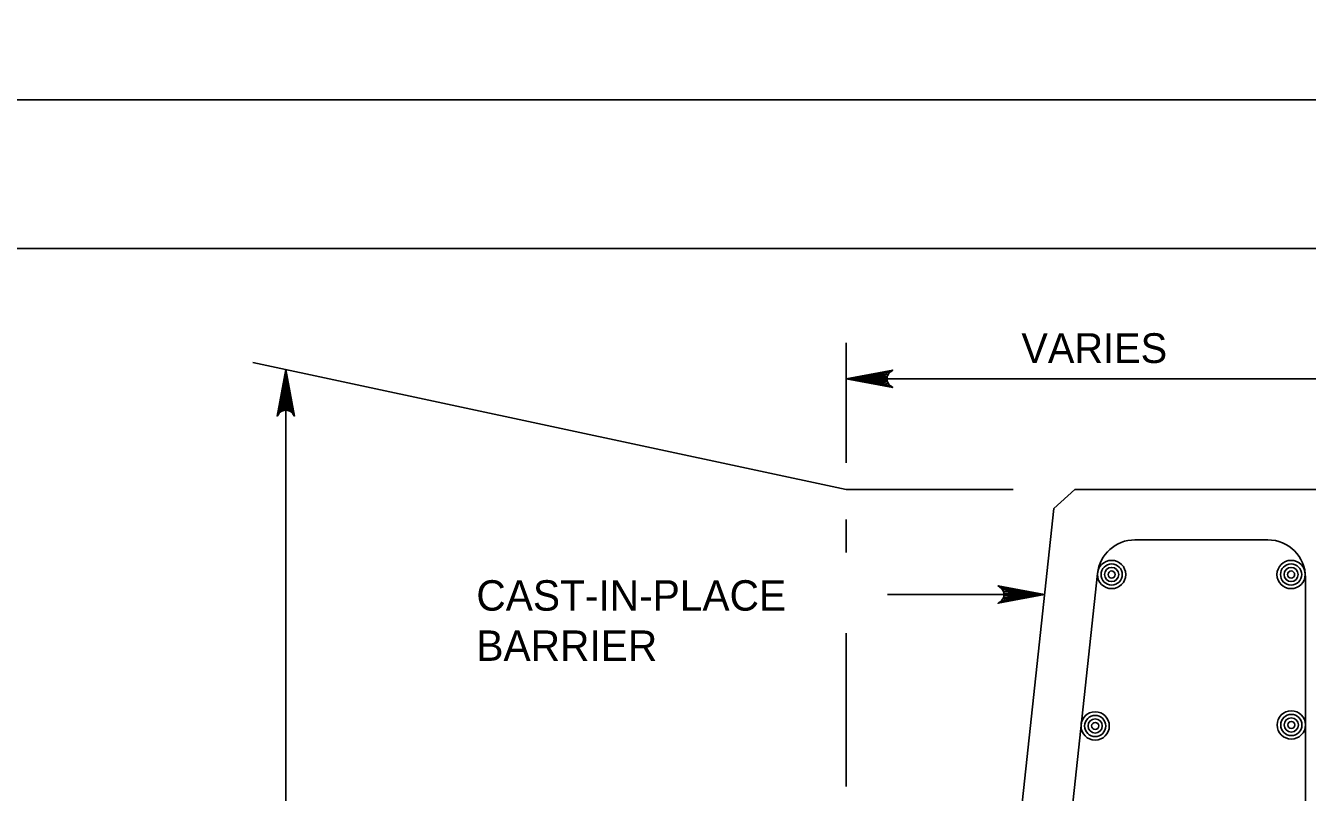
# Model space of a CAD drawing. Extents: x 638167 to 640248, y 296544 to 298920.
# Drawn here: x 639614.9 to 639744.3, y 297662.6 to 297740 of the extents above; entities that cross this region are included whole.
import ezdxf

# ---------------------------------------------------------------- set-up
doc = ezdxf.new("R2010")
doc.units = 0
for name, color, linetype in [('1', 7, 'Continuous'), ('50', 7, 'Continuous'), ('PLT-BNDY', 7, 'Continuous')]:
    doc.layers.add(name, color=color, linetype=linetype)

# ---------------------------------------------------------------- blocks, each defined once
blk = doc.blocks.new('BAR')
at = {"layer": '50'}
for radius in [2, 1.5, 1, 0.5]:
    blk.add_circle((0, 0), radius, dxfattribs=at)

msp = doc.modelspace()

# ---------------------------------------------------------------- linework, layer by layer
at = {"layer": '1'}
for p, q in [((639832.78, 297717.48), (639046.78, 297717.48)), ((639697.78, 297695.85), (639697.78, 297707.94)), ((639697.78, 297693.14), (639637.88, 297705.96)), ((639641.2, 297587.07), (639641.2, 297705.25)), ((639697.78, 297704.31), (639749.22, 297704.31)), ((639697.78, 297693.14), (639714.63, 297693.14)), ((639720.84, 297693.14), (639718.74, 297691.24)), ((639747.31, 297693.14), (639720.84, 297693.14)), ((639718.74, 297691.24), (639710.86, 297618.23)), ((639697.78, 297686.79), (639697.78, 297690.11)), ((639740.33, 297688.06), (639726.93, 297688.06)), ((639723.14, 297684.65), (639714.09, 297600.83)), ((639744.14, 297622.52), (639744.14, 297684.25)), ((639717.8, 297682.53), (639701.93, 297682.53)), ((639697.78, 297663.17), (639697.78, 297678.63))]:
    msp.add_line(p, q, dxfattribs=at)
for points in [[(639641.2, 297705.25), (639642.08, 297700.55), (639641.96, 297700.73), (639641.83, 297700.91), (639641.67, 297701.01), (639641.52, 297701.1), (639641.36, 297701.13), (639641.2, 297701.15), (639641.04, 297701.13), (639640.89, 297701.1), (639640.73, 297701.01), (639640.57, 297700.91), (639640.45, 297700.73), (639640.32, 297700.55), (639641.2, 297705.25), (639640.45, 297700.73), (639640.57, 297700.91), (639641.2, 297705.25), (639640.73, 297701.01), (639640.89, 297701.1), (639641.2, 297705.25), (639641.04, 297701.13), (639641.2, 297701.15), (639641.2, 297705.25), (639641.36, 297701.13), (639641.52, 297701.1), (639641.2, 297705.25), (639641.67, 297701.01), (639641.83, 297700.91), (639641.2, 297705.25), (639641.96, 297700.73)], [(639697.78, 297704.31), (639702.48, 297705.2), (639702.3, 297705.07), (639702.12, 297704.94), (639702.03, 297704.79), (639701.93, 297704.63), (639701.91, 297704.47), (639701.88, 297704.31), (639701.91, 297704.16), (639701.93, 297704), (639702.03, 297703.84), (639702.12, 297703.68), (639702.3, 297703.56), (639702.48, 297703.43), (639697.78, 297704.31), (639702.3, 297703.56), (639702.12, 297703.68), (639697.78, 297704.31), (639702.03, 297703.84), (639701.93, 297704), (639697.78, 297704.31), (639701.91, 297704.16), (639701.88, 297704.31), (639697.78, 297704.31), (639701.91, 297704.47), (639701.93, 297704.63), (639697.78, 297704.31), (639702.03, 297704.79), (639702.12, 297704.94), (639697.78, 297704.31), (639702.3, 297705.07)], [(639717.8, 297682.53), (639713.1, 297681.65), (639713.28, 297681.77), (639713.46, 297681.9), (639713.56, 297682.06), (639713.65, 297682.21), (639713.68, 297682.37), (639713.7, 297682.53), (639713.68, 297682.69), (639713.65, 297682.84), (639713.56, 297683), (639713.46, 297683.16), (639713.28, 297683.28), (639713.1, 297683.41), (639717.8, 297682.53), (639713.28, 297683.28), (639713.46, 297683.16), (639717.8, 297682.53), (639713.56, 297683), (639713.65, 297682.84), (639717.8, 297682.53), (639713.68, 297682.69), (639713.7, 297682.53), (639717.8, 297682.53), (639713.68, 297682.37), (639713.65, 297682.21), (639717.8, 297682.53), (639713.56, 297682.06), (639713.46, 297681.9), (639717.8, 297682.53), (639713.28, 297681.77)]]:
    msp.add_lwpolyline(points, dxfattribs=at)
for centre, start, end in [((639726.93, 297684.25), 90, 173.8367), ((639740.33, 297684.25), 0, 90)]:
    msp.add_arc(centre, 3.81, start, end, dxfattribs=at)
at = {"layer": 'PLT-BNDY'}
for points in [[(639007.78, 298326.48), (639848.78, 298326.48), (639848.78, 297732.48), (639007.78, 297732.48)], [(639007.78, 297732.48), (639848.78, 297732.48), (639848.78, 297138.48), (639007.78, 297138.48)]]:
    msp.add_lwpolyline(points, close=True, dxfattribs=at)

# ---------------------------------------------------------------- block references
at = {"layer": '1', "xscale": 0.714376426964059, "yscale": -0.714376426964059, "rotation": -89.99999999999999}
for p in [(639724.57, 297684.56), (639742.69, 297684.56), (639722.91, 297669.27), (639742.71, 297669.37)]:
    msp.add_blockref('BAR', p, dxfattribs=at)

# ---------------------------------------------------------------- texts
at = {"layer": '1'}
msp.add_text('VARIES', height=3, dxfattribs=at).set_placement((639715.46, 297705.92))
for s, p in [('CAST-IN-PLACE', (639660.44, 297680.91)), ('BARRIER', (639660.44, 297675.84))]:
    msp.add_text(s, height=3.072, rotation=360, dxfattribs=at).set_placement(p)

doc.saveas('drawing.dxf')
